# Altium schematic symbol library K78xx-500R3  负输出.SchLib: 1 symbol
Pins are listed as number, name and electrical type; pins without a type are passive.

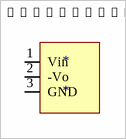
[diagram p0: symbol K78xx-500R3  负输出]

## K78xx-500R3  负输出
designator *
footprint K78xx-500R3 负输出
pins: 1 Vin, 2 -Vo, 3 GND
